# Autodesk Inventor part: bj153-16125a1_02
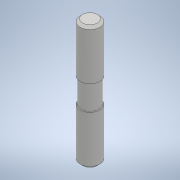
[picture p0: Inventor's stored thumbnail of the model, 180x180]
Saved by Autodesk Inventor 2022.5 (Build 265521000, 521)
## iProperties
Part Number: bj153-16125a1_02
Material: 一般
Document SubType Name: Modeling
Designer: ImaoCorp
Density: 1 g/cm^3
Appearance: 既定
Author: ImaoCorp
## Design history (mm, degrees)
feature "bj153-16125a1_02"
node "ソリッド1"
